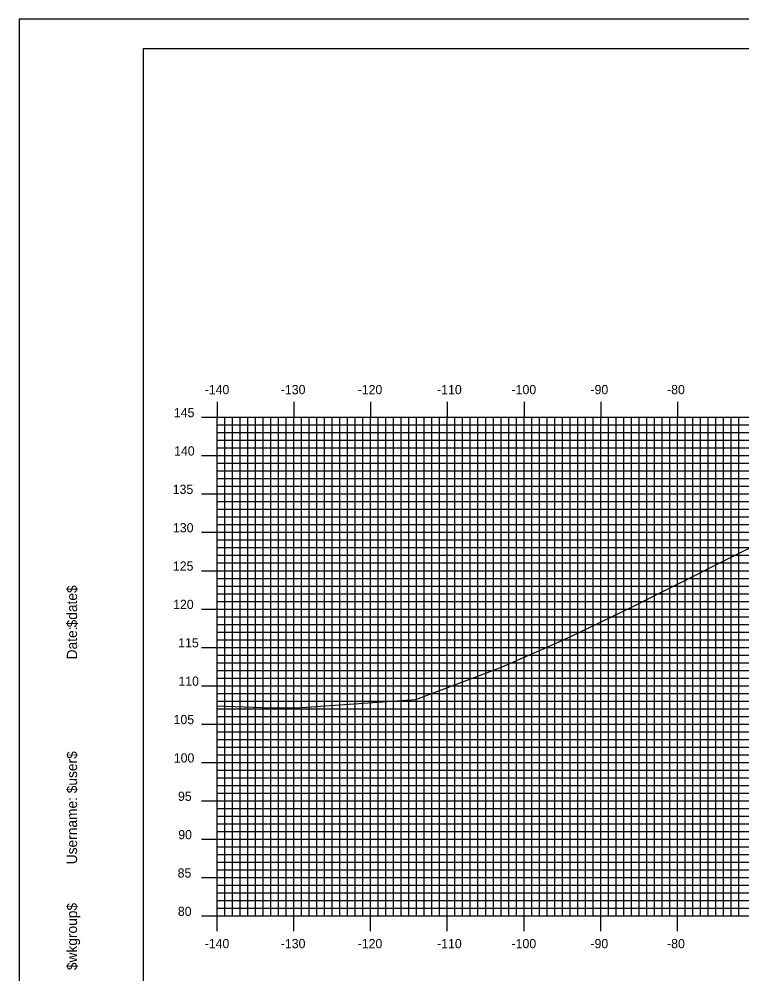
# Model space of a CAD drawing. Extents: x 859471 to 859814, y 364765 to 364985.
# Drawn here: x 859471.1 to 859565.3, y 364860.7 to 364985.2 of the extents above; entities that cross this region are included whole.
import ezdxf

# ---------------------------------------------------------------- set-up
doc = ezdxf.new("R2010")
doc.units = 0
for name, color, linetype in [('BORDER', 7, 'Continuous'), ('H_V ANNOTATION', 7, 'Continuous'), ('MAJOR', 7, 'Continuous'), ('MINOR', 7, 'Continuous'), ('PLOT BOUNDARY', 7, 'Continuous'), ('S_Roadway_Centerline', 7, 'Continuous')]:
    doc.layers.add(name, color=color, linetype=linetype)

msp = doc.modelspace()

# ---------------------------------------------------------------- linework, layer by layer
at = {"layer": 'BORDER'}
msp.add_lwpolyline([(859487.27, 364771.3), (859807.27, 364771.3), (859807.27, 364981.3), (859487.27, 364981.3)], close=True, dxfattribs=at)
at = {"layer": 'MAJOR'}
for p, q in [((859496.87, 364935.31), (859496.87, 364933.3)), ((859506.87, 364935.31), (859506.87, 364933.3)), ((859516.87, 364935.31), (859516.87, 364933.3)), ((859526.87, 364935.31), (859526.87, 364933.3)), ((859536.87, 364935.31), (859536.87, 364933.3)), ((859546.87, 364935.31), (859546.87, 364933.3)), ((859556.87, 364935.31), (859556.87, 364933.3)), ((859494.87, 364933.3), (859496.87, 364933.3)), ((859496.87, 364933.3), (859776.87, 364933.3)), ((859496.87, 364868.3), (859496.87, 364933.3)), ((859496.87, 364868.3), (859496.87, 364933.3)), ((859496.87, 364933.3), (859776.87, 364933.3)), ((859506.87, 364868.3), (859506.87, 364933.3)), ((859516.87, 364868.3), (859516.87, 364933.3)), ((859526.87, 364868.3), (859526.87, 364933.3)), ((859536.87, 364868.3), (859536.87, 364933.3)), ((859546.87, 364868.3), (859546.87, 364933.3)), ((859556.87, 364868.3), (859556.87, 364933.3)), ((859494.87, 364928.3), (859496.87, 364928.3)), ((859496.87, 364928.3), (859776.87, 364928.3)), ((859494.87, 364923.3), (859496.87, 364923.3)), ((859496.87, 364923.3), (859776.87, 364923.3)), ((859494.87, 364918.3), (859496.87, 364918.3)), ((859496.87, 364918.3), (859776.87, 364918.3)), ((859494.87, 364913.3), (859496.87, 364913.3)), ((859496.87, 364913.3), (859776.87, 364913.3)), ((859494.87, 364908.3), (859496.87, 364908.3)), ((859496.87, 364908.3), (859776.87, 364908.3)), ((859494.87, 364903.3), (859496.87, 364903.3)), ((859496.87, 364903.3), (859776.87, 364903.3)), ((859494.87, 364898.3), (859496.87, 364898.3)), ((859496.87, 364898.3), (859776.87, 364898.3)), ((859494.87, 364893.3), (859496.87, 364893.3)), ((859496.87, 364893.3), (859776.87, 364893.3)), ((859494.87, 364888.3), (859496.87, 364888.3)), ((859496.87, 364888.3), (859776.87, 364888.3)), ((859494.87, 364883.3), (859496.87, 364883.3)), ((859496.87, 364883.3), (859776.87, 364883.3)), ((859494.87, 364878.3), (859496.87, 364878.3)), ((859496.87, 364878.3), (859776.87, 364878.3)), ((859494.87, 364873.3), (859496.87, 364873.3)), ((859496.87, 364873.3), (859776.87, 364873.3)), ((859494.87, 364868.3), (859496.87, 364868.3)), ((859496.87, 364868.3), (859776.87, 364868.3)), ((859496.87, 364868.3), (859776.87, 364868.3)), ((859496.87, 364866.3), (859496.87, 364868.3)), ((859506.87, 364866.3), (859506.87, 364868.3)), ((859516.87, 364866.3), (859516.87, 364868.3)), ((859526.87, 364866.3), (859526.87, 364868.3)), ((859536.87, 364866.3), (859536.87, 364868.3)), ((859546.87, 364866.3), (859546.87, 364868.3)), ((859556.87, 364866.3), (859556.87, 364868.3))]:
    msp.add_line(p, q, dxfattribs=at)
at = {"layer": 'MINOR'}
for p, q in [((859496.87, 364932.3), (859776.87, 364932.3)), ((859496.87, 364932.3), (859498.88, 364932.3)), ((859497.87, 364868.3), (859497.87, 364933.3)), ((859498.87, 364868.3), (859498.87, 364933.3)), ((859499.87, 364868.3), (859499.87, 364933.3)), ((859500.87, 364868.3), (859500.87, 364933.3)), ((859501.87, 364868.3), (859501.87, 364933.3)), ((859502.87, 364868.3), (859502.87, 364933.3)), ((859503.87, 364868.3), (859503.87, 364933.3)), ((859504.87, 364868.3), (859504.87, 364933.3)), ((859505.87, 364868.3), (859505.87, 364933.3)), ((859507.87, 364868.3), (859507.87, 364933.3)), ((859508.87, 364868.3), (859508.87, 364933.3)), ((859509.87, 364868.3), (859509.87, 364933.3)), ((859510.87, 364868.3), (859510.87, 364933.3)), ((859511.87, 364868.3), (859511.87, 364933.3)), ((859512.87, 364868.3), (859512.87, 364933.3)), ((859513.87, 364868.3), (859513.87, 364933.3)), ((859514.87, 364868.3), (859514.87, 364933.3)), ((859515.87, 364868.3), (859515.87, 364933.3)), ((859517.87, 364868.3), (859517.87, 364933.3)), ((859518.87, 364868.3), (859518.87, 364933.3)), ((859519.87, 364868.3), (859519.87, 364933.3)), ((859520.87, 364868.3), (859520.87, 364933.3)), ((859521.87, 364868.3), (859521.87, 364933.3)), ((859522.87, 364868.3), (859522.87, 364933.3)), ((859523.87, 364868.3), (859523.87, 364933.3)), ((859524.87, 364868.3), (859524.87, 364933.3)), ((859525.87, 364868.3), (859525.87, 364933.3)), ((859527.87, 364868.3), (859527.87, 364933.3)), ((859528.87, 364868.3), (859528.87, 364933.3)), ((859529.87, 364868.3), (859529.87, 364933.3)), ((859530.87, 364868.3), (859530.87, 364933.3)), ((859531.87, 364868.3), (859531.87, 364933.3)), ((859532.87, 364868.3), (859532.87, 364933.3)), ((859533.87, 364868.3), (859533.87, 364933.3)), ((859534.87, 364868.3), (859534.87, 364933.3)), ((859535.87, 364868.3), (859535.87, 364933.3)), ((859537.87, 364868.3), (859537.87, 364933.3)), ((859538.87, 364868.3), (859538.87, 364933.3)), ((859539.87, 364868.3), (859539.87, 364933.3)), ((859540.87, 364868.3), (859540.87, 364933.3)), ((859541.87, 364868.3), (859541.87, 364933.3)), ((859542.87, 364868.3), (859542.87, 364933.3)), ((859543.87, 364868.3), (859543.87, 364933.3)), ((859544.87, 364868.3), (859544.87, 364933.3)), ((859545.87, 364868.3), (859545.87, 364933.3)), ((859547.87, 364868.3), (859547.87, 364933.3)), ((859548.87, 364868.3), (859548.87, 364933.3)), ((859549.87, 364868.3), (859549.87, 364933.3)), ((859550.87, 364868.3), (859550.87, 364933.3)), ((859551.87, 364868.3), (859551.87, 364933.3)), ((859552.87, 364868.3), (859552.87, 364933.3)), ((859553.87, 364868.3), (859553.87, 364933.3)), ((859554.87, 364868.3), (859554.87, 364933.3)), ((859555.87, 364868.3), (859555.87, 364933.3)), ((859557.87, 364868.3), (859557.87, 364933.3)), ((859558.87, 364868.3), (859558.87, 364933.3)), ((859559.87, 364868.3), (859559.87, 364933.3)), ((859560.87, 364868.3), (859560.87, 364933.3)), ((859561.87, 364868.3), (859561.87, 364933.3)), ((859562.87, 364868.3), (859562.87, 364933.3)), ((859563.87, 364868.3), (859563.87, 364933.3)), ((859564.87, 364868.3), (859564.87, 364933.3)), ((859496.87, 364931.3), (859776.87, 364931.3)), ((859496.87, 364931.3), (859498.88, 364931.3)), ((859496.87, 364930.3), (859776.87, 364930.3)), ((859496.87, 364930.3), (859498.88, 364930.3)), ((859496.87, 364929.3), (859776.87, 364929.3)), ((859496.87, 364929.3), (859498.88, 364929.3)), ((859496.87, 364927.3), (859776.87, 364927.3)), ((859496.87, 364927.3), (859498.88, 364927.3)), ((859496.87, 364926.3), (859776.87, 364926.3)), ((859496.87, 364926.3), (859498.88, 364926.3)), ((859496.87, 364925.3), (859776.87, 364925.3)), ((859496.87, 364925.3), (859498.88, 364925.3)), ((859496.87, 364924.3), (859776.87, 364924.3)), ((859496.87, 364924.3), (859498.88, 364924.3)), ((859496.87, 364922.3), (859776.87, 364922.3)), ((859496.87, 364922.3), (859498.88, 364922.3)), ((859496.87, 364921.3), (859776.87, 364921.3)), ((859496.87, 364921.3), (859498.88, 364921.3)), ((859496.87, 364920.3), (859776.87, 364920.3)), ((859496.87, 364920.3), (859498.88, 364920.3)), ((859496.87, 364919.3), (859776.87, 364919.3)), ((859496.87, 364919.3), (859498.88, 364919.3)), ((859496.87, 364917.3), (859776.87, 364917.3)), ((859496.87, 364917.3), (859498.88, 364917.3)), ((859496.87, 364916.3), (859776.87, 364916.3)), ((859496.87, 364916.3), (859498.88, 364916.3)), ((859496.87, 364915.3), (859776.87, 364915.3)), ((859496.87, 364915.3), (859498.88, 364915.3)), ((859496.87, 364914.3), (859776.87, 364914.3)), ((859496.87, 364914.3), (859498.88, 364914.3)), ((859496.87, 364912.3), (859776.87, 364912.3)), ((859496.87, 364912.3), (859498.88, 364912.3)), ((859496.87, 364911.3), (859776.87, 364911.3)), ((859496.87, 364911.3), (859498.88, 364911.3)), ((859496.87, 364910.3), (859776.87, 364910.3)), ((859496.87, 364910.3), (859498.88, 364910.3)), ((859496.87, 364909.3), (859776.87, 364909.3)), ((859496.87, 364909.3), (859498.88, 364909.3)), ((859496.87, 364907.3), (859776.87, 364907.3)), ((859496.87, 364907.3), (859498.88, 364907.3)), ((859496.87, 364906.3), (859776.87, 364906.3)), ((859496.87, 364906.3), (859498.88, 364906.3)), ((859496.87, 364905.3), (859776.87, 364905.3)), ((859496.87, 364905.3), (859498.88, 364905.3)), ((859496.87, 364904.3), (859776.87, 364904.3)), ((859496.87, 364904.3), (859498.88, 364904.3)), ((859496.87, 364902.3), (859776.87, 364902.3)), ((859496.87, 364902.3), (859498.88, 364902.3)), ((859496.87, 364901.3), (859776.87, 364901.3)), ((859496.87, 364901.3), (859498.88, 364901.3)), ((859496.87, 364900.3), (859776.87, 364900.3)), ((859496.87, 364900.3), (859498.88, 364900.3)), ((859496.87, 364899.3), (859776.87, 364899.3)), ((859496.87, 364899.3), (859498.88, 364899.3)), ((859496.87, 364897.3), (859776.87, 364897.3)), ((859496.87, 364897.3), (859498.88, 364897.3)), ((859496.87, 364896.3), (859776.87, 364896.3)), ((859496.87, 364896.3), (859498.88, 364896.3)), ((859496.87, 364895.3), (859776.87, 364895.3)), ((859496.87, 364895.3), (859498.88, 364895.3)), ((859496.87, 364894.3), (859776.87, 364894.3)), ((859496.87, 364894.3), (859498.88, 364894.3)), ((859496.87, 364892.3), (859776.87, 364892.3)), ((859496.87, 364892.3), (859498.88, 364892.3)), ((859496.87, 364891.3), (859776.87, 364891.3)), ((859496.87, 364891.3), (859498.88, 364891.3)), ((859496.87, 364890.3), (859776.87, 364890.3)), ((859496.87, 364890.3), (859498.88, 364890.3)), ((859496.87, 364889.3), (859776.87, 364889.3)), ((859496.87, 364889.3), (859498.88, 364889.3)), ((859496.87, 364887.3), (859776.87, 364887.3)), ((859496.87, 364887.3), (859498.88, 364887.3)), ((859496.87, 364886.3), (859776.87, 364886.3)), ((859496.87, 364886.3), (859498.88, 364886.3)), ((859496.87, 364885.3), (859776.87, 364885.3)), ((859496.87, 364885.3), (859498.88, 364885.3)), ((859496.87, 364884.3), (859776.87, 364884.3)), ((859496.87, 364884.3), (859498.88, 364884.3)), ((859496.87, 364882.3), (859776.87, 364882.3)), ((859496.87, 364882.3), (859498.88, 364882.3)), ((859496.87, 364881.3), (859776.87, 364881.3)), ((859496.87, 364881.3), (859498.88, 364881.3)), ((859496.87, 364880.3), (859776.87, 364880.3)), ((859496.87, 364880.3), (859498.88, 364880.3)), ((859496.87, 364879.3), (859776.87, 364879.3)), ((859496.87, 364879.3), (859498.88, 364879.3)), ((859496.87, 364877.3), (859776.87, 364877.3)), ((859496.87, 364877.3), (859498.88, 364877.3)), ((859496.87, 364876.3), (859776.87, 364876.3)), ((859496.87, 364876.3), (859498.88, 364876.3)), ((859496.87, 364875.3), (859776.87, 364875.3)), ((859496.87, 364875.3), (859498.88, 364875.3)), ((859496.87, 364874.3), (859776.87, 364874.3)), ((859496.87, 364874.3), (859498.88, 364874.3)), ((859496.87, 364872.3), (859776.87, 364872.3)), ((859496.87, 364872.3), (859498.88, 364872.3)), ((859496.87, 364871.3), (859776.87, 364871.3)), ((859496.87, 364871.3), (859498.88, 364871.3)), ((859496.87, 364870.3), (859776.87, 364870.3)), ((859496.87, 364870.3), (859498.88, 364870.3)), ((859496.87, 364869.3), (859776.87, 364869.3)), ((859496.87, 364869.3), (859498.88, 364869.3))]:
    msp.add_line(p, q, dxfattribs=at)
at = {"layer": 'PLOT BOUNDARY'}
msp.add_lwpolyline([(859471.09, 364765.18), (859811.09, 364765.18), (859811.09, 364985.18), (859471.09, 364985.18)], close=True, dxfattribs=at)
at = {"layer": 'S_Roadway_Centerline'}
msp.add_lwpolyline([(859496.87, 364895.67), (859502.75, 364895.48), (859507.25, 364895.43), (859522.77, 364896.52), (859533.73, 364900.64), (859539.17, 364903.01), (859542.98, 364904.71), (859550.76, 364908.5), (859569.5, 364917.87), (859574.24, 364920.22), (859586.41, 364921), (859594.04, 364921.52), (859623.68, 364922.44), (859624.88, 364922.48), (859625.49, 364922.49), (859626.93, 364922.5), (859644.46, 364922.65), (859661.25, 364915.33)], dxfattribs=at)

# ---------------------------------------------------------------- texts
at = {"layer": 'BORDER'}
for s, p in [('$date$', (859478.64, 364905.91)), ('Date:', (859478.64, 364901.74)), ('$user$', (859478.64, 364884.29)), ('Username:', (859478.64, 364875.04)), ('$wkgroup$', (859478.64, 364861.24))]:
    msp.add_text(s, height=1.339, rotation=90, dxfattribs=at).set_placement(p)
at = {"layer": 'H_V ANNOTATION'}
for s, p in [('-140', (859495.26, 364936.3)), ('-130', (859505.18, 364936.3)), ('-120', (859515.19, 364936.3)), ('-110', (859525.54, 364936.3)), ('-100', (859535.24, 364936.3)), ('-90', (859545.52, 364936.3)), ('-80', (859555.5, 364936.3)), ('145', (859491.25, 364933.3)), ('140', (859491.28, 364928.3)), ('135', (859491.1, 364923.3)), ('130', (859491.13, 364918.3)), ('125', (859491.12, 364913.3)), ('120', (859491.15, 364908.3)), ('115', (859491.81, 364903.3)), ('110', (859491.84, 364898.3)), ('105', (859491.21, 364893.3)), ('100', (859491.24, 364888.3)), ('95', (859491.79, 364883.3)), ('90', (859491.82, 364878.3)), ('85', (859491.74, 364873.3)), ('80', (859491.77, 364868.3)), ('-140', (859495.26, 364864.1)), ('-130', (859505.18, 364864.1)), ('-120', (859515.19, 364864.1)), ('-110', (859525.54, 364864.1)), ('-100', (859535.24, 364864.1)), ('-90', (859545.52, 364864.1)), ('-80', (859555.5, 364864.1))]:
    msp.add_text(s, height=1.2, dxfattribs=at).set_placement(p)
at = {"layer": 'MAJOR'}
msp.add_text('-', height=0.012, dxfattribs=at).set_placement((859496.86, 364868.3))

doc.saveas('drawing.dxf')
